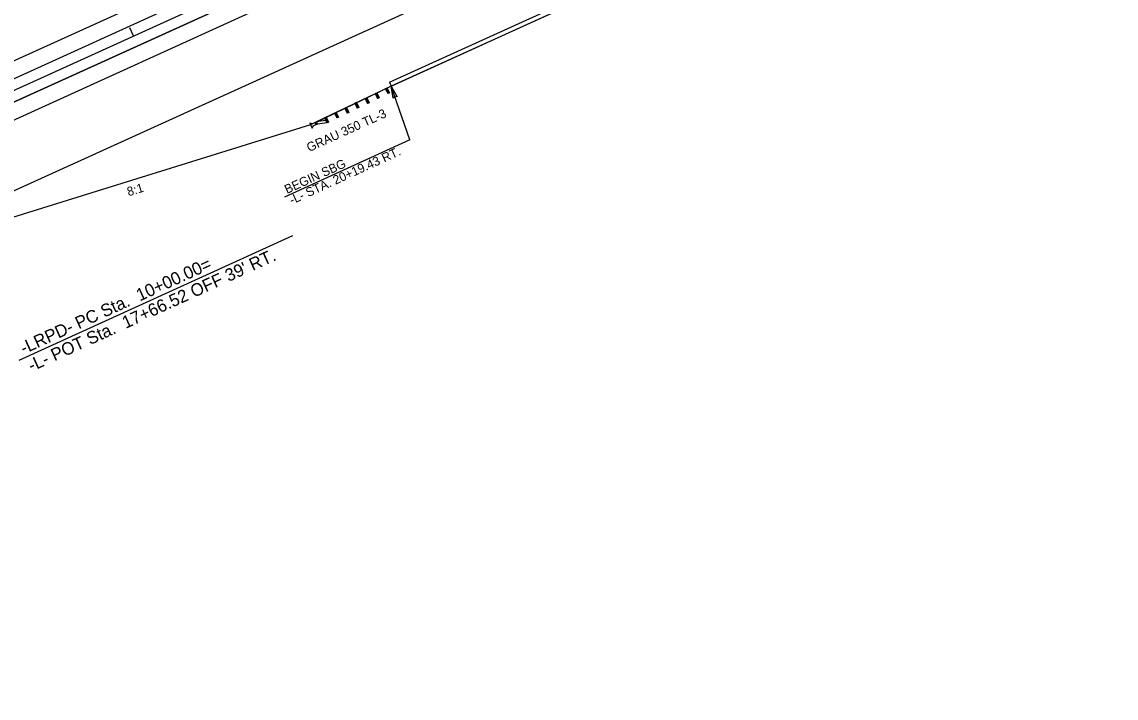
# Model space of a CAD drawing. Extents: x 2242984 to 2250974, y 661492 to 664681.
# Drawn here: x 2248440 to 2249051, y 662790 to 663168 of the extents above; entities that cross this region are included whole.
import ezdxf

# ---------------------------------------------------------------- set-up
doc = ezdxf.new("R2010")
doc.units = 0
for name, color, linetype in [('Prop Conc Shoulder Berm Gutter', 7, 'Continuous'), ('Prop Dimension Text', 7, 'Continuous'), ('Prop DSN Text', 7, 'Continuous'), ('Prop EOT', 7, 'Continuous'), ('Prop Guardrail', 7, 'Continuous'), ('Prop Guardrail Anchor Unit CELL', 7, 'Continuous'), ('Prop Horizontal Alignment', 7, 'Continuous'), ('Prop Horizontal Alignment Station Label', 7, 'Continuous'), ('Prop Horizontal Alignment Tick Small', 7, 'Continuous'), ('Prop Paved Shoulder', 7, 'Continuous'), ('Prop Terminator CELL', 7, 'Continuous'), ('Scratch_Level_6', 7, 'Continuous'), ('Scratch_Level_8', 7, 'Continuous')]:
    doc.layers.add(name, color=color, linetype=linetype)

msp = doc.modelspace()

# ---------------------------------------------------------------- linework, layer by layer
at = {"layer": 'Prop Conc Shoulder Berm Gutter'}
for q in [(2248878.26, 663239.94), (2248646.2, 663131.96)]:
    msp.add_line((2248645.24, 663134.09), q, dxfattribs=at)
at = {"layer": 'Prop DSN Text'}
for q in [(2248646.2, 663131.96), (2248586.66, 663069.94)]:
    msp.add_line((2248656.71, 663101.87), q, dxfattribs=at)
at = {"layer": 'Prop EOT'}
for p, q in [((2248200.21, 663039.2), (2249433.89, 663599.6)), ((2248212.61, 663011.89), (2249446.3, 663572.29)), ((2248401.88, 663058.32), (2249188.04, 663415.44))]:
    msp.add_line(p, q, dxfattribs=at)
at = {"layer": 'Prop Guardrail'}
for p, q in [((2248855.32, 663313.72), (2247994.71, 662922.79)), ((2248855.32, 663313.72), (2247994.71, 662922.79)), ((2247989.75, 662933.71), (2248810.53, 663306.55)), ((2247989.75, 662933.71), (2248810.53, 663306.55)), ((2248646.2, 663131.96), (2248885.14, 663240.5))]:
    msp.add_line(p, q, dxfattribs=at)
at = {"layer": 'Prop Guardrail Anchor Unit CELL'}
for p, q in [((2248646.2, 663131.96), (2248604.03, 663111.78)), ((2248637.32, 663127.71), (2248638.64, 663124.96)), ((2248638.88, 663126.77), (2248637.32, 663127.71)), ((2248638.23, 663128.14), (2248637.98, 663126.33)), ((2248638.88, 663126.77), (2248637.98, 663126.33)), ((2248638.23, 663128.14), (2248639.54, 663125.39)), ((2248638.64, 663124.96), (2248638.88, 663126.77)), ((2248643.91, 663130.86), (2248643.01, 663130.43)), ((2248643.01, 663130.43), (2248644.3, 663127.73)), ((2248643.01, 663130.43), (2248643.65, 663129.08)), ((2248644.56, 663129.51), (2248643.01, 663130.43)), ((2248643.65, 663129.08), (2248643.91, 663130.86)), ((2248644.56, 663129.51), (2248643.65, 663129.08)), ((2248643.65, 663129.08), (2248645.2, 663128.16)), ((2248643.91, 663130.86), (2248645.2, 663128.16)), ((2248644.3, 663127.73), (2248644.56, 663129.51)), ((2248645.2, 663128.16), (2248644.3, 663127.73)), ((2248626.86, 663122.7), (2248625.96, 663122.27)), ((2248625.96, 663122.27), (2248627.27, 663119.53)), ((2248627.51, 663121.33), (2248625.96, 663122.27)), ((2248626.86, 663122.7), (2248626.61, 663120.9)), ((2248627.51, 663121.33), (2248626.61, 663120.9)), ((2248626.61, 663120.9), (2248628.17, 663119.96)), ((2248626.86, 663122.7), (2248628.17, 663119.96)), ((2248627.27, 663119.53), (2248627.51, 663121.33)), ((2248631.64, 663124.99), (2248632.96, 663122.24)), ((2248633.2, 663124.05), (2248631.64, 663124.99)), ((2248632.54, 663125.42), (2248632.3, 663123.62)), ((2248633.2, 663124.05), (2248632.3, 663123.62)), ((2248632.3, 663123.62), (2248633.86, 663122.67)), ((2248632.54, 663125.42), (2248633.86, 663122.67)), ((2248632.96, 663122.24), (2248633.2, 663124.05)), ((2248633.86, 663122.67), (2248632.96, 663122.24)), ((2248637.98, 663126.33), (2248639.54, 663125.39)), ((2248639.54, 663125.39), (2248638.64, 663124.96)), ((2248609.81, 663114.54), (2248609.57, 663112.73)), ((2248609.81, 663114.54), (2248611.13, 663111.78)), ((2248614.59, 663116.83), (2248615.88, 663114.12)), ((2248616.14, 663115.91), (2248614.59, 663116.83)), ((2248615.49, 663117.26), (2248615.24, 663115.48)), ((2248616.14, 663115.91), (2248615.24, 663115.48)), ((2248615.24, 663115.48), (2248616.79, 663114.56)), ((2248615.49, 663117.26), (2248616.79, 663114.56)), ((2248615.88, 663114.12), (2248616.14, 663115.91)), ((2248616.79, 663114.56), (2248615.88, 663114.12)), ((2248620.27, 663119.55), (2248621.63, 663116.72)), ((2248621.85, 663118.57), (2248620.27, 663119.55)), ((2248621.17, 663119.98), (2248620.95, 663118.14)), ((2248621.85, 663118.57), (2248620.95, 663118.14)), ((2248620.95, 663118.14), (2248622.53, 663117.15)), ((2248621.17, 663119.98), (2248622.53, 663117.15)), ((2248621.63, 663116.72), (2248621.85, 663118.57)), ((2248622.53, 663117.15), (2248621.63, 663116.72)), ((2248628.17, 663119.96), (2248627.27, 663119.53)), ((2248602.17, 663110.85), (2248600.75, 663111.14)), ((2248600.75, 663111.14), (2248601.97, 663108.47)), ((2248601.97, 663108.47), (2248602.68, 663109.74)), ((2248604.04, 663111.7), (2248602.17, 663110.85)), ((2248602.68, 663109.74), (2248604.54, 663110.59)), ((2248603.58, 663111.56), (2248604.23, 663110.21)), ((2248603.58, 663111.56), (2248605.13, 663110.64)), ((2248604.29, 663111.14), (2248604.04, 663111.7)), ((2248604.23, 663110.21), (2248604.48, 663111.99)), ((2248605.13, 663110.64), (2248604.23, 663110.21)), ((2248604.54, 663110.59), (2248604.29, 663111.14)), ((2248609.57, 663112.73), (2248604.48, 663111.99)), ((2248604.48, 663111.99), (2248605.13, 663110.64)), ((2248605.13, 663110.64), (2248604.68, 663110.43)), ((2248610.23, 663111.35), (2248605.13, 663110.64)), ((2248608.9, 663114.11), (2248610.23, 663111.35)), ((2248610.47, 663113.16), (2248608.9, 663114.11)), ((2248610.47, 663113.16), (2248609.57, 663112.73)), ((2248609.57, 663112.73), (2248611.13, 663111.78)), ((2248610.23, 663111.35), (2248610.47, 663113.16)), ((2248611.13, 663111.78), (2248610.23, 663111.35))]:
    msp.add_line(p, q, dxfattribs=at)
at = {"layer": 'Prop Horizontal Alignment'}
msp.add_line((2247500.8, 662705.02), (2249793.08, 663746.29), dxfattribs=at)
at = {"layer": 'Prop Horizontal Alignment Station Label'}
msp.add_line((2248591, 663048.38), (2248438.16, 662978.73), dxfattribs=at)
at = {"layer": 'Prop Horizontal Alignment Tick Small'}
msp.add_line((2248502.31, 663159.96), (2248500.24, 663164.51), dxfattribs=at)
at = {"layer": 'Prop Paved Shoulder'}
for p, q in [((2248203.91, 663031), (2248894.79, 663344.83)), ((2248208.89, 663020.08), (2248895.78, 663332.1)), ((2248646.2, 663131.96), (2248879.23, 663237.81)), ((2248646.2, 663131.96), (2248601.09, 663110.37)), ((2248601.09, 663110.37), (2248370.21, 663038.44))]:
    msp.add_line(p, q, dxfattribs=at)
at = {"layer": 'Prop Terminator CELL'}
msp.add_lwpolyline([(2248647.33, 663125.21), (2248646.2, 663131.96), (2248649.57, 663125.95), (2248648.16, 663126.37)], close=True, dxfattribs=at)
at = {"layer": 'Scratch_Level_6'}
for p, q in [((2248902.31, 663248.19), (2248646.24, 663131.87)), ((2248646.24, 663131.87), (2248604.08, 663111.69))]:
    msp.add_line(p, q, dxfattribs=at)
at = {"layer": 'Scratch_Level_8'}
msp.add_line((2248880.54, 663238.31), (2248646.24, 663131.88), dxfattribs=at)

# ---------------------------------------------------------------- texts
at = {"layer": 'Prop Dimension Text'}
msp.add_text('8:1', height=5, rotation=16.6387, dxfattribs=at).set_placement((2248499.46, 663070.4))
at = {"layer": 'Prop DSN Text'}
for s, p in [('-L- STA. 20+19.43 RT.', (2248590.71, 663065.72)), ('BEGIN SBG', (2248587.99, 663071.69))]:
    msp.add_text(s, height=5, rotation=24.49794, dxfattribs=at).set_placement(p)
at = {"layer": 'Prop Guardrail Anchor Unit CELL'}
msp.add_text('GRAU 350 TL-3', height=5, rotation=24.43013, dxfattribs=at).set_placement((2248600.38, 663095.05))
at = {"layer": 'Prop Horizontal Alignment Station Label'}
for s, p in [("-L- POT Sta.  17+66.52 OFF 39' RT.", (2248445.31, 662972.41)), ('-LRPD- PC Sta.  10+00.00=', (2248440.89, 662982.11))]:
    msp.add_text(s, height=7, rotation=24.49794, dxfattribs=at).set_placement(p)

doc.saveas('drawing.dxf')
